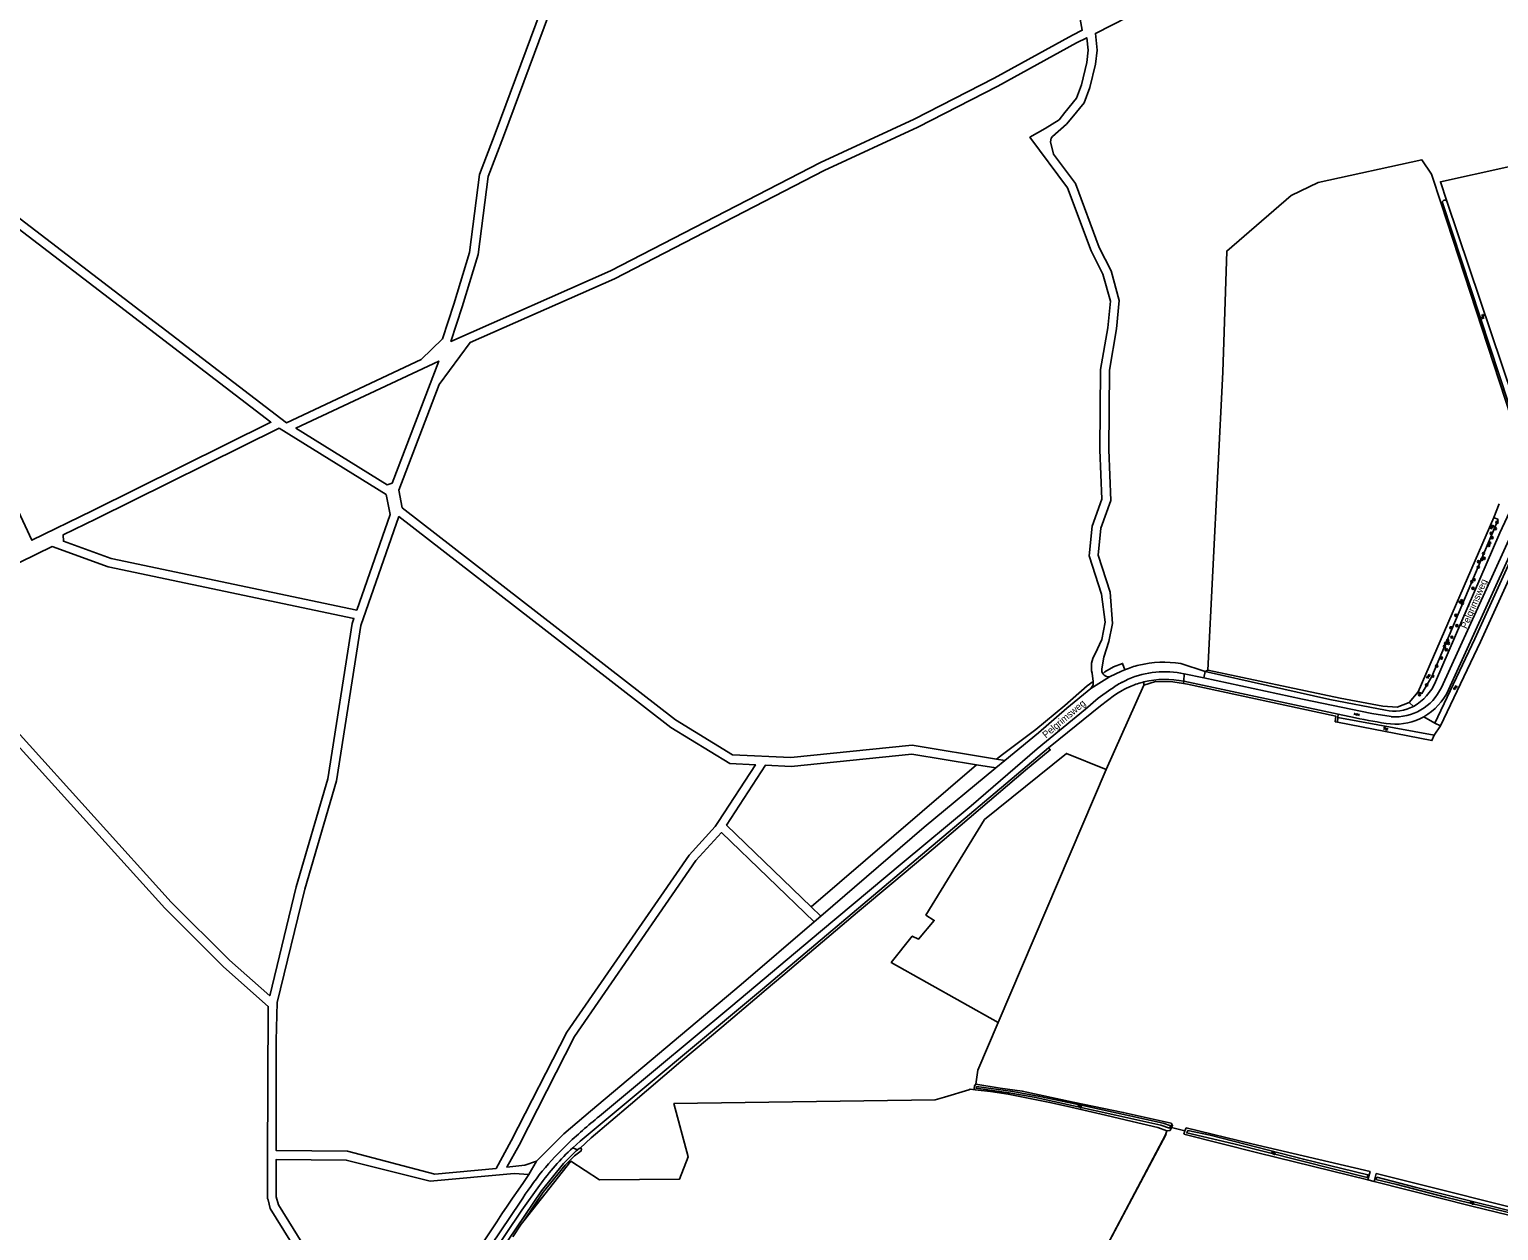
# Model space of a CAD drawing. Extents: x 134297 to 137000, y 403500 to 406000.
# Drawn here: x 134816 to 135347, y 404706 to 405141 of the extents above; entities that cross this region are included whole.
import ezdxf

# ---------------------------------------------------------------- set-up
doc = ezdxf.new("R2010")
doc.units = 0
for name, color, linetype in [('gg-afsc-draadraster', 7, 'Continuous'), ('gg-afsc-lijn draadraster', 7, 'Continuous'), ('gg-anno-openbare ruimte label', 7, 'Continuous'), ('gg-knt-bronhoudergrens', 7, 'Continuous'), ('gg-knt-onverhard', 7, 'Continuous'), ('gg-knt-verharding', 7, 'Continuous'), ('gg-kntw-bovenkant insteek waterloop', 7, 'Continuous'), ('gg-kntw-waterlijn', 7, 'Continuous'), ('gt-grn-groengrens', 7, 'Continuous'), ('gt-symb-boom', 7, 'Continuous'), ('gt-symb-gesloten verharding', 7, 'Continuous'), ('gt-symb-watersymbool', 7, 'Continuous'), ('gx-grn-maaiveld', 7, 'Continuous')]:
    doc.layers.add(name, color=color, linetype=linetype)

# ---------------------------------------------------------------- blocks, each defined once
blk = doc.blocks.new('gt0-WA')
at = {"layer": 'gt-symb-watersymbool'}
for centre, start, end in [((-0.32, 0.02), 28.0725, 151.9275), ((0.43, 0.42), 208.0725, 331.9275), ((-0.32, -0.43), 28.0725, 151.9275), ((0.43, -0.03), 208.0725, 331.9275)]:
    blk.add_arc(centre, 0.425, start, end, dxfattribs=at)
blk = doc.blocks.new('gt0-BOOM')
at = {"layer": 'gt-symb-boom'}
for radius in [0.4, 0.2]:
    blk.add_circle((0, 0), radius, dxfattribs=at)
blk = doc.blocks.new('gt0-GESVH1')
at = {"layer": 'gt-symb-gesloten verharding'}
for p, q in [((-0.99, -0.26), (0.01, 0.24)), ((0.01, -0.26), (-0.99, 0.24)), ((0.01, 0.24), (1.01, -0.26)), ((1.01, 0.24), (0.01, -0.26))]:
    blk.add_line(p, q, dxfattribs=at)

msp = doc.modelspace()

# ---------------------------------------------------------------- linework, layer by layer
at = {"layer": 'gg-afsc-draadraster'}
for points in [[(135232.84, 404904.3), (135234.32, 404904.05), (135287.91, 404892.53), (135287.72, 404890.49), (135288.5, 404890.33)], [(135157.81, 404759.39), (135158.49, 404764.47), (135165.85, 404781.76)], [(135157.54, 404757.4), (135155.77, 404757.6), (135155.21, 404757.44)]]:
    msp.add_lwpolyline(points, dxfattribs=at)
at = {"layer": 'gg-afsc-lijn draadraster'}
for points in [[(135232.84, 404904.3), (135234.32, 404904.05), (135287.91, 404892.53), (135287.72, 404890.49), (135288.5, 404890.33)], [(135157.81, 404759.39), (135158.49, 404764.47), (135165.85, 404781.76)], [(135157.54, 404757.4), (135155.77, 404757.6), (135155.21, 404757.44)], [(135174.52, 404642.37), (135200.84, 404692.83), (135226.58, 404741.37)]]:
    msp.add_lwpolyline(points, dxfattribs=at)
at = {"layer": 'gg-knt-bronhoudergrens'}
for p, q in [((135240.24, 404906.32), (135240.74, 404908.66)), ((135240.74, 404908.66), (135241.62, 404909.17)), ((135232.84, 404904.3), (135232.97, 404905.12)), ((135165.85, 404781.76), (135204.84, 404873.17)), ((135155.21, 404757.44), (135146.43, 404754.8)), ((135233.37, 404742.57), (135228.54, 404743.81)), ((135299.46, 404724.83), (135301.75, 404724.27))]:
    msp.add_line(p, q, dxfattribs=at)
for points in [[(135328.12, 405078.68), (135325.76, 405085.72), (135373.76, 405096.28)], [(135196.94, 404685.34), (135200.84, 404692.83), (135226.36, 404741.19), (135226.84, 404742.53)]]:
    msp.add_lwpolyline(points, dxfattribs=at)
at = {"layer": 'gg-knt-onverhard'}
msp.add_lwpolyline([(135324.03, 404904.94), (135347.24, 404958.83), (135356.9, 404979.43)], dxfattribs=at)
msp.add_arc((135306.73, 404912.4), 18.84, 299.7175, 336.6647, dxfattribs=at)
at = {"layer": 'gg-knt-verharding'}
for p, q in [((135362.61, 404982.93), (135326.1, 404902.92)), ((135364.98, 404981.97), (135328.66, 404902)), ((135288.77, 404893.23), (135232.97, 404905.12)), ((135295.01, 404891.9), (135288.77, 404893.23))]:
    msp.add_line(p, q, dxfattribs=at)
msp.add_lwpolyline([(135307.97, 404892.33), (135301, 404893.44), (135275.92, 404898.68), (135240.24, 404906.32)], dxfattribs=at)
for centre, radius, start, end in [((135309.52, 404910.48), 18.22, 265.1191, 335.4696), ((135309.4, 404910.77), 21.16, 299.2665, 335.5067), ((135331.38, 405062.42), 174.35, 257.9608, 262.1909), ((135309.41, 404910.77), 21.15, 265.3495, 299.2629)]:
    msp.add_arc(centre, radius, start, end, dxfattribs=at)
at = {"layer": 'gg-kntw-bovenkant insteek waterloop'}
for p, q in [((135355.98, 404995.66), (135328.12, 405078.68)), ((135317.74, 404901.26), (135345.02, 404964.39)), ((135288.5, 404890.33), (135288.65, 404891.97)), ((135323.46, 404885.63), (135288.65, 404891.97)), ((135325.84, 404888.99), (135323.77, 404890.03)), ((135233.37, 404742.57), (135232.93, 404741.4)), ((135233.37, 404742.57), (135233.8, 404743.72))]:
    msp.add_line(p, q, dxfattribs=at)
for points in [[(135323.77, 404890.03), (135338.22, 404920.42), (135364.73, 404978.76)], [(135366.79, 404977.72), (135340.28, 404919.38), (135325.84, 404888.99)], [(135345.02, 404964.39), (135346.61, 404963.61), (135322.71, 404906.84), (135319.07, 404900.71), (135317.74, 404901.26)], [(135323.46, 404885.63), (135322.69, 404883.68), (135288.5, 404890.33)], [(135157.54, 404757.4), (135157.17, 404757.87), (135157.3, 404758.89), (135157.81, 404759.39)], [(135157.81, 404759.39), (135166.62, 404758.05), (135174.53, 404756.95), (135192.98, 404752.99), (135211.05, 404749.21), (135228.38, 404745.36)], [(135226.84, 404742.53), (135223.62, 404743.73), (135214.31, 404746), (135204.65, 404748.26), (135190.5, 404751.5), (135184.49, 404752.78), (135169.49, 404755.84), (135163.1, 404756.78), (135157.54, 404757.4)], [(135226.84, 404742.53), (135228.01, 404742.74), (135228.54, 404743.81)], [(135228.54, 404743.81), (135228.9, 404744.53), (135228.38, 404745.36)], [(135299.46, 404724.83), (135300.31, 404727.89), (135257.58, 404737.82), (135233.8, 404743.72)], [(135232.93, 404741.4), (135259.78, 404734.59), (135299.46, 404724.83)], [(135301.75, 404724.27), (135302.57, 404727.11), (135369.36, 404710.38)], [(135301.75, 404724.27), (135337.13, 404715.36), (135368.8, 404707.6)]]:
    msp.add_lwpolyline(points, dxfattribs=at)
at = {"layer": 'gg-kntw-waterlijn'}
for points in [[(135157.99, 404758.63), (135171.11, 404756.77), (135180.86, 404755), (135196.42, 404751.75), (135225.5, 404745.3), (135228.28, 404744.39), (135227.74, 404743.52), (135224.64, 404744.64), (135208.37, 404748.28), (135178.8, 404754.69), (135169.74, 404756.36), (135157.9, 404757.98), (135157.99, 404758.63)], [(135234.43, 404742.68), (135242.46, 404740.97), (135276.24, 404732.31), (135299.51, 404726.65), (135299.29, 404725.76), (135251.09, 404737.84), (135234.03, 404741.8), (135234.43, 404742.68)], [(135302.8, 404725.82), (135316.68, 404722.26), (135368.76, 404709.22), (135368.57, 404708.49), (135353.81, 404712.18), (135327.6, 404718.59), (135309.97, 404723.16), (135302.37, 404724.96), (135302.8, 404725.82)]]:
    msp.add_lwpolyline(points, dxfattribs=at)
at = {"layer": 'gt-grn-groengrens'}
for p, q in [((135346.96, 404969.29), (135345.02, 404964.39)), ((135314.47, 404897.51), (135317.74, 404901.26)), ((135316.07, 404896.04), (135314.47, 404897.51)), ((135288.65, 404891.97), (135288.77, 404893.23)), ((135323.77, 404890.03), (135319.75, 404892.31)), ((135323.46, 404885.63), (135325.84, 404888.99))]:
    msp.add_line(p, q, dxfattribs=at)
msp.add_lwpolyline([(135314.47, 404897.51), (135310.09, 404895.79), (135304.91, 404896.17), (135289.5, 404899.02), (135241.62, 404909.17)], dxfattribs=at)
at = {"layer": 'gx-grn-maaiveld'}
for p, q in [((135326.07, 405077.88), (135326.53, 405078.06)), ((135326.07, 405077.88), (135355.57, 404987.59)), ((135326.53, 405078.06), (135353.83, 404995.12)), ((135199.33, 404902.56), (135206.14, 404906.72)), ((135199.82, 404908.02), (135200.23, 404905.06)), ((135231.86, 404911.52), (135240.74, 404908.66)), ((135233.08, 404907.85), (135232.97, 404905.12)), ((135233.08, 404907.85), (135240.24, 404906.32)), ((135218.48, 404903.73), (135204.84, 404873.17)), ((135218.48, 404903.73), (135218.55, 404904.89)), ((135098.21, 404823.57), (135158, 404874.93)), ((135158, 404874.93), (135165, 404873.78)), ((135168.27, 404876.48), (135165, 404873.78)), ((135168.27, 404876.48), (135165.24, 404876.98)), ((135101.69, 404820.22), (135098.21, 404823.57)), ((135101.69, 404820.22), (135099.25, 404818.12)), ((135012.03, 404736.45), (135013.68, 404735.7)), ((134998.93, 404731.55), (134996.1, 404726.76))]:
    msp.add_line(p, q, dxfattribs=at)
for points in [[(135193.68, 405154.62), (135196.27, 405140.55), (135192.71, 405138.75), (135164.39, 405123.22), (135135.41, 405108.34), (135101.58, 405092.72), (135025.68, 405053.52), (134967.96, 405027.99), (134972.02, 405040.56), (134977.87, 405059.42), (134981.39, 405087.59), (134986.98, 405102.09), (135003.55, 405146.86)], [(134698, 405149.39), (134709.39, 405134.84), (134720.11, 405122.33), (134741.76, 405100.55), (134751.5, 405089.49), (134758.28, 405090.21), (134772.78, 405098.33), (134779.77, 405095.36), (134793.05, 405086.91), (134908.45, 404998.58), (134957.25, 405021.49), (134964.89, 405028.89), (134968.97, 405041.52), (134974.73, 405060.1), (134978.27, 405088.38), (134983.99, 405103.22), (135000.54, 405147.95)], [(135212.88, 405145.37), (135201.01, 405139.36), (135201.62, 405133.33), (135201.02, 405128.28), (135199.02, 405119.86), (135196.93, 405114.32), (135192.48, 405108.81), (135190.55, 405106.59), (135185.49, 405102.06), (135185.02, 405101.45), (135184.81, 405100.21), (135185.89, 405095.7), (135193.8, 405085.1), (135202.42, 405061.99), (135206.67, 405053.53), (135209.64, 405042.83), (135208.63, 405032.5), (135206.07, 405017.57), (135205.8, 404988.85), (135206.53, 404970.45), (135203.01, 404960.51), (135201.99, 404950.77), (135206.33, 404937.3), (135207.21, 404926), (135205.85, 404919.54), (135204, 404913.86), (135203.31, 404909.64)], [(135165.24, 404876.98), (135134.78, 404881.99), (135090.93, 404877.57), (135069.81, 404878.57), (135049.17, 404891.16), (134950.28, 404967.85), (134949.15, 404974.27), (134963.72, 405012.4), (134974.9, 405027.56), (135027.07, 405050.63), (135102.92, 405089.81), (135136.81, 405105.47), (135165.75, 405120.32), (135194.2, 405135.92), (135197.89, 405137.79), (135198.4, 405133.33), (135197.86, 405128.84), (135195.96, 405120.8), (135194.12, 405115.93), (135189.99, 405110.82), (135187.92, 405108.15), (135182.83, 405104.95), (135177.34, 405101.81), (135190.96, 405083.55), (135199.48, 405060.71), (135203.67, 405052.37), (135206.4, 405042.55), (135205.46, 405032.93), (135202.87, 405017.86), (135202.6, 404988.8), (135203.31, 404970.94), (135199.87, 404961.22), (135198.74, 404950.43), (135203.17, 404936.68), (135204.58, 404926.45), (135203.38, 404920.28), (135200.94, 404915.02)], [(134772.97, 405094.77), (134778.28, 405092.52), (134791.22, 405084.28), (134902.9, 404998.8), (134838.24, 404966.77), (134816.48, 404956.1), (134755.56, 405086.71), (134759.27, 405087.1), (134772.97, 405094.77)], [(135241.62, 404909.17), (135247.07, 405016.89), (135248.48, 405060.65), (135271.81, 405080.78), (135281.6, 405085.41), (135319.04, 405093.61), (135322.48, 405088.46), (135326.07, 405077.88)], [(135326.53, 405078.06), (135326.5, 405078.24), (135326.51, 405078.36), (135326.56, 405078.58), (135326.63, 405078.72), (135326.77, 405078.89), (135326.88, 405078.99), (135327.02, 405079.06), (135327.16, 405079.11), (135327.31, 405079.13), (135327.46, 405079.12), (135327.68, 405079.07), (135327.87, 405078.96), (135328.03, 405078.8), (135328.12, 405078.68)], [(134946.69, 404976.79), (134944.93, 404976.17), (134911.9, 404996.67), (134963.54, 405020.9), (134946.69, 404976.79)], [(134905.82, 404996.68), (134944.55, 404972.63), (134946.04, 404965.42), (134933.93, 404930.89), (134845.08, 404949.54), (134827.82, 404955.75), (134827.8, 404958.08), (134839.65, 404963.89), (134905.82, 404996.68)], [(135007.64, 404919.33), (135047.51, 404888.43), (135068.84, 404875.41), (135078.07, 404874.97), (135064.67, 404854.47), (135063.49, 404852.66), (135054.05, 404842.3), (135009.85, 404778.29), (134989.79, 404738.93), (134984.29, 404728.97), (134962.17, 404726.92), (134930.53, 404735.2), (134904.81, 404735.45), (134904.8, 404775.29), (134905.17, 404789), (134915.15, 404829.94), (134926.64, 404869.14), (134935.35, 404925.27), (134949.16, 404964.66), (135007.64, 404919.33)], [(134844, 404946.53), (134932.86, 404927.85), (134932.23, 404926.05), (134923.51, 404869.84), (134912.06, 404830.77), (134902.46, 404791.39), (134887.91, 404804.24), (134866.81, 404825.23), (134811.11, 404886.92), (134783.86, 404912.5), (134758.97, 404922.21), (134823.8, 404953.8), (134844, 404946.53)], [(134662.77, 404873.92), (134709.41, 404898.07), (134755.06, 404920.31), (134782.12, 404909.74), (134808.83, 404884.68), (134864.49, 404823.03), (134885.72, 404801.9), (134901.93, 404787.59), (134901.68, 404731.86), (134901.68, 404718.1), (134901.82, 404717.58), (134902.63, 404714.52), (134926.76, 404675.71), (134926.49, 404661.64)], [(135203.67, 404907.86), (135204.42, 404908.51), (135207.55, 404910.33), (135210.84, 404911.57), (135211.69, 404909.31)], [(135206.14, 404906.72), (135210.47, 404908.79), (135211.69, 404909.31)], [(135240.74, 404908.66), (135285.74, 404898.58), (135305.87, 404894.64)], [(135022.45, 404748.48), (135041.99, 404764.81), (135069.22, 404787.38), (135101.55, 404814.7), (135131.1, 404839.37), (135156.1, 404860.07), (135179.94, 404880.64), (135197.42, 404895.09), (135202.06, 404898.99), (135206.53, 404902.22)], [(135165.24, 404876.98), (135167.36, 404878.64), (135179.49, 404887.73), (135189.91, 404896.41), (135198.08, 404903.48), (135200.23, 404905.06)], [(135168.27, 404876.48), (135180.4, 404886.52), (135190.67, 404895.44), (135199.33, 404902.56)], [(135184.08, 404881), (135187.73, 404884.07), (135202.9, 404896.25), (135207.94, 404900.1), (135209.27, 404900.98), (135210.65, 404901.78)], [(135210.58, 404904.74), (135211.73, 404905.32), (135212.9, 404905.86)], [(135218.48, 404903.73), (135222.77, 404905.02), (135229.02, 404904.93), (135232.84, 404904.3)], [(135184.08, 404881), (135080.58, 404793.85), (135014.67, 404738.78), (135012.03, 404736.45)], [(135014.64, 404736.28), (135018.68, 404739.99), (135032.9, 404752.11), (135051.13, 404767.59), (135065.87, 404780.05), (135077.83, 404790.19), (135081.97, 404793.64), (135088.02, 404798.77), (135097.58, 404806.93), (135105.42, 404813.58), (135115, 404821.66), (135128.17, 404832.64), (135142.28, 404844.56), (135175.75, 404872.96), (135184.65, 404880.29), (135184.08, 404881)], [(135098.21, 404823.57), (135067.61, 404853.12), (135081.77, 404874.8), (135091.02, 404874.37), (135134.68, 404878.77), (135158, 404874.93)], [(135204.84, 404873.17), (135190.55, 404879.03), (135160.94, 404855.12), (135139.69, 404820.58), (135142.72, 404818.68), (135137.03, 404811.85), (135134.75, 404812.99), (135127.16, 404803.5), (135165.85, 404781.76)], [(135165, 404873.78), (135139.08, 404852.33), (135101.69, 404820.22)], [(135099.25, 404818.12), (135065.79, 404850.43), (135056.56, 404840.3), (135012.6, 404776.64), (134992.62, 404737.43), (134988.2, 404729.43), (134994.63, 404730.18), (134998.93, 404731.55)], [(135099.25, 404818.12), (135072.89, 404795.48), (135018.46, 404749.69), (135008.83, 404741.45), (134998.93, 404731.55)], [(134994.28, 404710), (135011.36, 404731.6), (135021.68, 404724.86), (135050.65, 404725.12), (135053.7, 404733.19), (135048.59, 404752.46), (135143.01, 404753.77), (135146.43, 404754.8)], [(135014.64, 404736.28), (135014.88, 404736.34), (135015.14, 404735.99), (135015.03, 404735.34), (135012.64, 404733.59), (135009.26, 404730.22), (135001.3, 404720.38), (134994.28, 404710)], [(135013.68, 404735.7), (135014.29, 404736.18), (135014.64, 404736.28)], [(134996.1, 404726.76), (134990.86, 404727.18), (134960.47, 404724.36), (134930.11, 404732.01), (134904.81, 404732.25), (134904.82, 404718.74), (134905.6, 404715.81), (134930.02, 404676.54), (134929.09, 404661.13)], [(134925.31, 404562.22), (134925.3, 404563.66), (134925.55, 404572.58), (134926.42, 404584.92), (134927.66, 404593.7), (134930.33, 404604.04), (134932.11, 404609.68), (134935.03, 404616.23), (134939.98, 404625.76), (134956.53, 404653.95), (134976.62, 404685.25), (135000.68, 404720.83), (135008.69, 404730.74), (135012.1, 404734.14), (135013.26, 404735.38), (135013.68, 404735.7)], [(134929.66, 404607.83), (134932.57, 404615.57), (134934.44, 404620.02), (134938.37, 404627.79), (134941.92, 404634.27), (134945.43, 404640.19), (134949.87, 404647.48), (134958.2, 404660.61), (134969.84, 404678.14), (134981.85, 404696.3), (134993.58, 404713.92), (135000, 404722.81)], [(134931.69, 404619.76), (134935.47, 404627), (134938.19, 404632.11), (134941.43, 404638.04), (134952.89, 404656.66), (134975.56, 404690.83), (134993, 404716.76)], [(134990.4, 404704.26), (134993.37, 404708.85), (134994.28, 404710)]]:
    msp.add_lwpolyline(points, dxfattribs=at)
for centre, radius, start, end in [((135208.28, 404910.25), 8.75, 147.0077, 194.7957), ((135225.66, 404874.92), 37.12, 80.3859, 103.9341), ((135205.77, 404909.2), 2.5, 169.9585, 212.5996), ((135205.78, 404909.2), 2.51, 212.4763, 278.1586), ((135225.74, 404874.65), 37.41, 103.9629, 112.0712), ((135226.11, 404875.3), 33.29, 77.9109, 113.3743), ((135197.29, 404904.71), 2.96, 313.4539, 345.9687), ((135197.29, 404904.71), 2.96, 346.037, 6.9037), ((135225.82, 404875.81), 32.71, 117.7814, 126.1479), ((135226.13, 404873.94), 31.86, 112.4089, 119.075), ((135226.26, 404873.69), 32.14, 103.8791, 112.4475), ((135226.27, 404873.63), 32.2, 77.978, 103.8653), ((135308.93, 404910.18), 15.85, 258.8493, 296.7687), ((135132.85, 404609.01), 177.88, 128.3669, 133.5031), ((135082.6, 404661.2), 105.43, 133.2145, 148.195), ((135070.28, 404672.96), 86.17, 132.5368, 144.6509), ((136639.96, 403599.17), 1993.42, 145.5521, 148.71794)]:
    msp.add_arc(centre, radius, start, end, dxfattribs=at)

# ---------------------------------------------------------------- block references
at = {"layer": 'gt-symb-boom'}
for p in [(135345.58, 404960.29), (135346.24, 404962.59), (135343.26, 404954.24), (135343.56, 404955.17), (135344.1, 404958.61), (135344.38, 404957.05), (135339.53, 404948.39), (135340.74, 404949.25), (135341.32, 404951.31), (135341.56, 404949.55), (135339.47, 404946.37), (135337.11, 404941.11), (135337.52, 404938.73), (135337.89, 404941.88), (135333.66, 404933.28), (135331.32, 404928.98), (135329.61, 404924.47), (135331.71, 404925.21), (135327.22, 404917.74), (135327.64, 404918.85), (135327.86, 404916.59), (135328.4, 404919.86), (135328.69, 404918.81), (135329.89, 404921.08), (135326.11, 404913.54), (135323, 404906.97), (135324.43, 404910.66), (135320.77, 404903.75), (135318.18, 404900.31)]:
    msp.add_blockref('gt0-BOOM', p, dxfattribs=at)
at = {"layer": 'gt-symb-gesloten verharding', "rotation": 167.29726808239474}
msp.add_blockref('gt0-GESVH1', (135295.53, 404893.15), dxfattribs=at)
at = {"layer": 'gt-symb-watersymbool'}
for p, rotation in [((135341.1, 405036.96), 108.2356914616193), ((135344.37, 404960.81), 73.97589034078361), ((135333.07, 404934), 67.04963698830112), ((135321.39, 404906.84), 73.97589034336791), ((135331.09, 404902.8), 73.97589034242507), ((135305.91, 404887.94), -2.9796737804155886), ((135195.42, 404751.42), 167.11702052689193), ((135265.3, 404734.59), -13.827795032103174), ((135337.13, 404716.55), -13.772145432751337)]:
    msp.add_blockref('gt0-WA', p, dxfattribs=dict(at, rotation=rotation))

# ---------------------------------------------------------------- texts
at = {"layer": 'gg-anno-openbare ruimte label'}
for rotation, p in [(66.7, (135335.23, 404923.89)), (40.3, (135183.13, 404884.42))]:
    msp.add_text('Pelgrimsweg', height=2.5, rotation=rotation, dxfattribs=at).set_placement(p)

doc.saveas('drawing.dxf')
